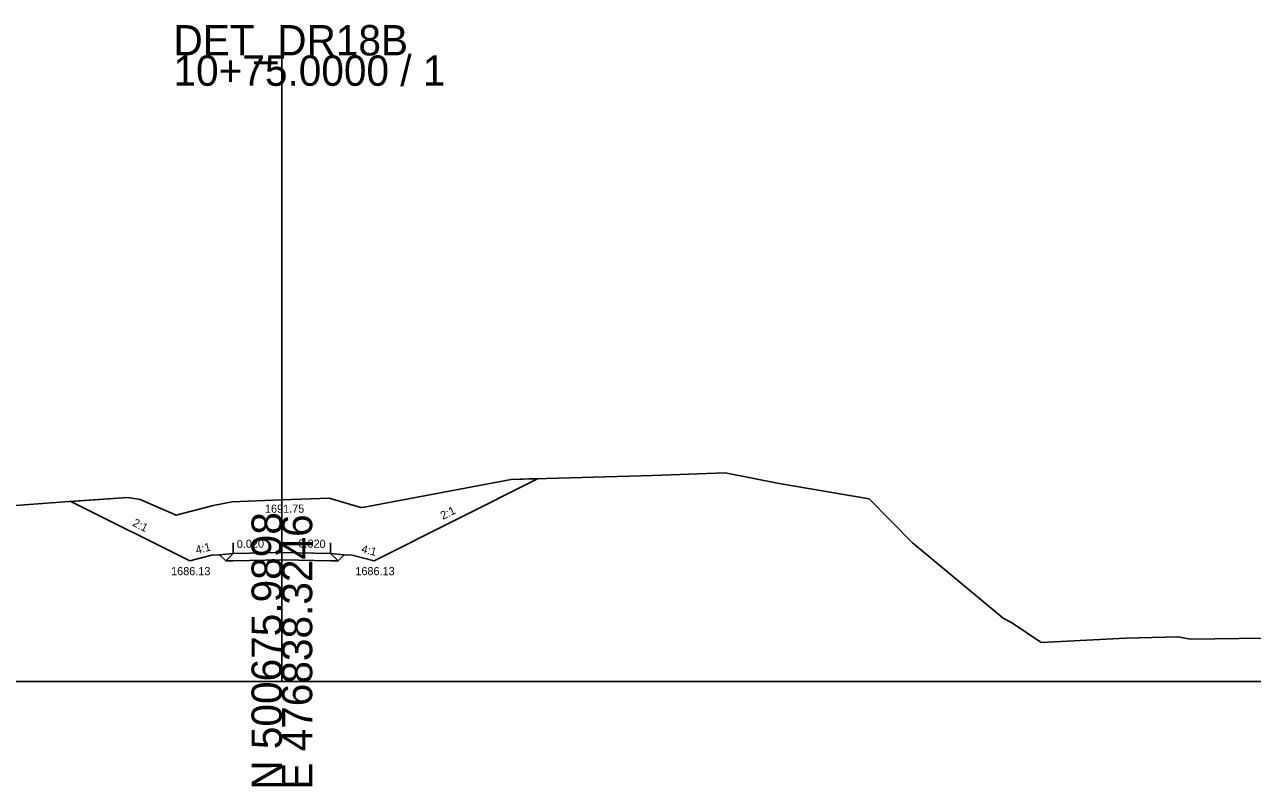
# Model space of a CAD drawing. Extents: x -26 to 403, y -10 to 2570.
# Drawn here: x 176.3 to 289.5, y 1490.3 to 1560.6 of the extents above; entities that cross this region are included whole.
import ezdxf

# ---------------------------------------------------------------- set-up
doc = ezdxf.new("R2010")
doc.units = 0
for name, color, linetype in [('Exist Cross Section Cell', 7, 'Continuous'), ('Exist XS Center Line Elevation Label', 7, 'Continuous'), ('Exist XS Ground Line', 7, 'Continuous'), ('Prop XS Ditch Slope Text', 7, 'Continuous'), ('Prop XS Ditch Standard Text', 7, 'Continuous'), ('Prop XS Dump Level', 7, 'Continuous'), ('Prop XS Earthwork Shape', 7, 'Continuous'), ('Prop XS EOT Tick Mark', 7, 'Continuous'), ('Prop XS Finish Grade', 7, 'Continuous'), ('Prop XS Finish Grade Earthwork', 7, 'Continuous'), ('Prop XS Finish Grade Pavement', 7, 'Continuous'), ('Prop XS Hydro Typical Ditch Data', 7, 'Continuous'), ('Prop XS Pvmt Edge Slope', 7, 'Continuous'), ('Prop XS SE Text', 7, 'Continuous'), ('Prop XS Shoulder Borrow Shape', 7, 'Continuous'), ('Prop XS Side Slope Text', 7, 'Continuous'), ('Prop XS Subgrade Earthwork', 7, 'Continuous')]:
    doc.layers.add(name, color=color, linetype=linetype)

msp = doc.modelspace()

# ---------------------------------------------------------------- linework, layer by layer
at = {"layer": 'Exist Cross Section Cell'}
for p, q in [((200, 1500), (200, 1557.73)), ((0, 1500), (200, 1500)), ((200, 1500), (400, 1500))]:
    msp.add_line(p, q, dxfattribs=at)
at = {"layer": 'Exist XS Ground Line'}
msp.add_lwpolyline([(170.87, 1515.87), (180.38, 1516.59), (185.78, 1516.97), (186.93, 1516.77), (190.25, 1515.32), (193.65, 1516.22), (195.4, 1516.55), (198.42, 1516.69), (200, 1516.75), (204.37, 1516.9), (207.29, 1516.03), (207.59, 1516.08), (221.16, 1518.63), (234.21, 1519), (240.9, 1519.24), (245.88, 1518.26), (254.18, 1516.82), (258.19, 1512.79), (266.55, 1505.83), (267.42, 1505.38), (270.07, 1503.59), (277.88, 1503.98), (282.71, 1504.12), (283.81, 1503.89), (290.6, 1503.98)], dxfattribs=at)
at = {"layer": 'Prop XS Dump Level'}
for p, q in [((200, 1511.88), (195.5, 1511.79)), ((195.5, 1511.79), (200, 1511.88)), ((204.5, 1511.79), (200, 1511.88)), ((200, 1511.88), (204.5, 1511.79))]:
    msp.add_line(p, q, dxfattribs=at)
at = {"layer": 'Prop XS Earthwork Shape'}
msp.add_lwpolyline([(185.78, 1516.97), (186.93, 1516.77), (190.25, 1515.32), (193.65, 1516.22), (195.4, 1516.55), (198.42, 1516.69), (200, 1516.75), (204.37, 1516.9), (207.29, 1516.03), (207.59, 1516.08), (221.16, 1518.63), (223.65, 1518.7), (208.5, 1511.13), (206.5, 1511.63), (205.76, 1511.68), (205.18, 1511.11), (204.5, 1511.12), (200, 1511.21), (195.5, 1511.12), (194.82, 1511.11), (194.24, 1511.68), (193.5, 1511.63), (191.5, 1511.13), (180.54, 1516.6)], close=True, dxfattribs=at)
at = {"layer": 'Prop XS EOT Tick Mark'}
for p, q in [((195.5, 1511.79), (195.5, 1512.79)), ((204.5, 1511.79), (204.5, 1512.79))]:
    msp.add_line(p, q, dxfattribs=at)
at = {"layer": 'Prop XS Finish Grade'}
for p, q in [((195.5, 1511.79), (194.24, 1511.68)), ((204.5, 1511.79), (205.76, 1511.68))]:
    msp.add_line(p, q, dxfattribs=at)
at = {"layer": 'Prop XS Finish Grade Earthwork'}
for p, q in [((208.5, 1511.13), (223.65, 1518.7)), ((191.5, 1511.13), (180.54, 1516.6)), ((193.5, 1511.63), (191.5, 1511.13)), ((194.24, 1511.68), (193.5, 1511.63)), ((205.76, 1511.68), (206.5, 1511.63)), ((206.5, 1511.63), (208.5, 1511.13))]:
    msp.add_line(p, q, dxfattribs=at)
at = {"layer": 'Prop XS Finish Grade Pavement'}
for p, q in [((195.5, 1511.79), (200, 1511.88)), ((200, 1511.88), (204.5, 1511.79))]:
    msp.add_line(p, q, dxfattribs=at)
at = {"layer": 'Prop XS Hydro Typical Ditch Data'}
for p, q in [((208.5, 1511.13), (223.65, 1518.7)), ((191.5, 1511.13), (180.54, 1516.6)), ((193.5, 1511.63), (191.5, 1511.13)), ((206.5, 1511.63), (208.5, 1511.13))]:
    msp.add_line(p, q, dxfattribs=at)
at = {"layer": 'Prop XS Pvmt Edge Slope'}
for p, q in [((195.5, 1511.79), (194.82, 1511.11)), ((204.5, 1511.79), (205.18, 1511.11))]:
    msp.add_line(p, q, dxfattribs=at)
at = {"layer": 'Prop XS Shoulder Borrow Shape'}
for points in [[(195.5, 1511.79), (194.82, 1511.11), (194.24, 1511.68)], [(205.18, 1511.11), (205.76, 1511.68), (204.5, 1511.79)]]:
    msp.add_lwpolyline(points, close=True, dxfattribs=at)
at = {"layer": 'Prop XS Subgrade Earthwork'}
for p, q in [((194.82, 1511.11), (194.24, 1511.68)), ((205.18, 1511.11), (205.76, 1511.68)), ((195.5, 1511.12), (194.82, 1511.11)), ((200, 1511.21), (195.5, 1511.12)), ((204.5, 1511.12), (200, 1511.21)), ((204.5, 1511.12), (205.18, 1511.11))]:
    msp.add_line(p, q, dxfattribs=at)

# ---------------------------------------------------------------- texts
at = {"layer": 'Exist Cross Section Cell'}
for s, p in [('DET_DR18B', (190, 1557.73)), ('10+75.0000 / 1', (190, 1554.93))]:
    msp.add_text(s, height=2.8, dxfattribs=at).set_placement(p)
for s, p in [('N 500675.9898', (200, 1490)), ('E 476838.3246', (202.8, 1490))]:
    msp.add_text(s, height=2.8, rotation=90, dxfattribs=at).set_placement(p)
at = {"layer": 'Exist XS Center Line Elevation Label'}
msp.add_text('1691.75', height=0.75, dxfattribs=at).set_placement((198.44, 1515.55))
at = {"layer": 'Prop XS Ditch Slope Text'}
for rotation, p in [(14.0362, (192.14, 1511.74)), (345.9638, (207.28, 1511.89))]:
    msp.add_text('4:1', height=0.75, rotation=rotation, dxfattribs=at).set_placement(p)
at = {"layer": 'Prop XS Ditch Standard Text'}
for p in [(189.78, 1509.79), (206.78, 1509.79)]:
    msp.add_text('1686.13', height=0.75, dxfattribs=at).set_placement(p)
at = {"layer": 'Prop XS Dump Level'}
for p in [(193.5, 1511.59), (206.5, 1511.59)]:
    msp.add_text('Case1', height=0.04, dxfattribs=at).set_placement(p)
at = {"layer": 'Prop XS SE Text'}
for rotation, p in [(1.1458, (195.85, 1512.29)), (358.8542, (201.52, 1512.35))]:
    msp.add_text('0.020', height=0.75, rotation=rotation, dxfattribs=at).set_placement(p)
at = {"layer": 'Prop XS Side Slope Text'}
for rotation, p in [(26.5651, (214.86, 1514.89)), (333.4349, (186.16, 1514.38))]:
    msp.add_text('2:1', height=0.75, rotation=rotation, dxfattribs=at).set_placement(p)

doc.saveas('drawing.dxf')
